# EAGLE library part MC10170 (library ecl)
9 Bit + 2-bin Parity Generation Checker
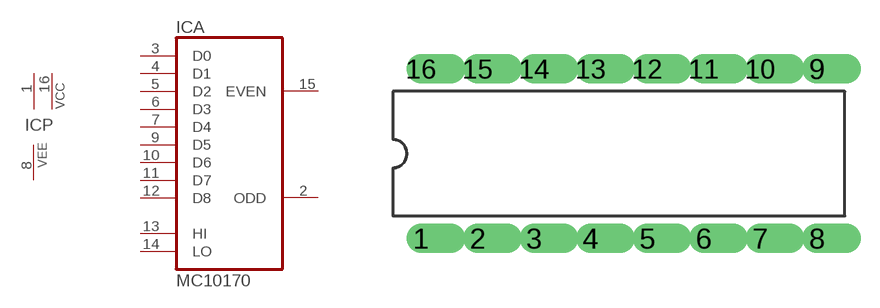
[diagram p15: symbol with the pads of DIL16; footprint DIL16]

Designator prefix IC; gates A=MC10170 P=2VCC1VEE

## MC10170  [DIL16]
1  P:VCC  pwr
2  A:ODD  out
3  A:D0  in
4  A:D1  in
5  A:D2  in
6  A:D3  in
7  A:D4  in
8  P:VEE  pwr
9  A:D5  in
10  A:D6  in
11  A:D7  in
12  A:D8  in
13  A:HI  in
14  A:LO  in
15  A:EVEN  out
16  P:VCC  pwr

## Footprint DIL16 (pad centres in mm)
drill 0.813 offset: 1 -8.89,-3.81; 2 -6.35,-3.81; 3 -3.81,-3.81; 4 -1.27,-3.81; 5 1.27,-3.81; 6 3.81,-3.81; 7 6.35,-3.81; 8 8.89,-3.81; 9 8.89,3.81; 10 6.35,3.81; 11 3.81,3.81; 12 1.27,3.81; 13 -1.27,3.81; 14 -3.81,3.81; 15 -6.35,3.81; 16 -8.89,3.81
